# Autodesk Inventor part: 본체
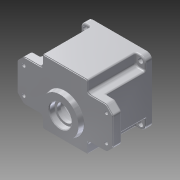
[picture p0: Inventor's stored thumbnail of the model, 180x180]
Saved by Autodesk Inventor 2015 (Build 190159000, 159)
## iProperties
Created: 2016-02
Part Number: 본체
Material: Aluminum 6061
Document SubType Name: Modeling
Designer: Administrator
Density: 2.7 g/cm^3
Appearance: Aluminum - Flat
Mass: 874.182 g
Surface Area: 763.255 cm^2
Volume: 323.771 cm^3
Author: Administrator
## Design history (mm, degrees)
sketch "Sketch1"
  geometry: L1 (-70, 30)-(-70, -30); L2 (70, -30)-(70, 30); L3 (33, 47)-(-33, 47); L4 (-33, -47)-(33, -47); L5 (70, 30)-(33, 30); L6 (-33, 30)-(-70, 30); L7 (33, -47)-(33, -30); L8 (33, 30)-(33, 47); L9 (-70, -30)-(-33, -30); L10 (33, -30)-(70, -30); L11 (-33, 47)-(-33, 30); L12 (-33, -30)-(-33, -47); 1 further point
  constraints: 24 end point, 10 parallel, 4 perpendicular, 3 collinear, 3 horizontal
  dimensions: "d0" = 140 distance between parallel lines of L1 L2; "d1" = 70 distance from line of point (0, 0) L2; "d2" = 94 distance between parallel lines of L4 L3; "d3" = 47 distance from line of L3 point (0, 0); "d4" = 66 distance between parallel lines of L11 L8; "d5" = 66 distance between parallel lines of L12 L7; "d6" = 33 distance from line of point (0, 0) L7; "d7" = 60 distance of L2.start L2.end; "d8" = 30 distance from line of point (0, 0) L5
extrude "Extrusion1" new body sketch "Sketch1" distance "d9" = 13; taper "d10" = 0 deg
sketch "Sketch2"
  geometry: L1 (-70, 30)-(-70, -30) reference; L2 (-70, -30)-(-33, -30) reference; L3 (-33, -30)-(-33, -47) reference; L4 (-33, -47)-(33, -47) reference; L5 (33, -47)-(33, -30) reference; L6 (33, -30)-(70, -30) reference; L7 (70, -30)-(70, 30) reference; L8 (70, 30)-(33, 30) reference; L9 (33, 30)-(33, 47) reference; L10 (33, 47)-(-33, 47) reference; L11 (-33, 47)-(-33, 30) reference; L12 (-33, 30)-(-70, 30) reference; L13 (47, 47)-(-47, 47); L14 (-47, 47)-(-47, -47); L15 (-47, -47)-(47, -47); L16 (47, -47)-(47, 47); L17 (47, 47)-(-47, -47); L18 (-47, 47)-(47, -47); 1 further point
  constraints: 12 end point, 2 midpoint, 2 parallel, 1 horizontal, 1 perpendicular
  dimensions: "d11" = 94 distance of L15.end L14.end; "d12" = 94 distance of L14.end L13.end
extrude "Extrusion2" join sketch "Sketch2" distance "d13" = 67; taper "d14" = 0 deg
sketch "Sketch4"
  geometry: L1 (-70, 30)-(-70, -30) reference; L2 (-70, -30)-(-33, -30) reference; L3 (-33, -30)-(-33, -47) reference; L4 (-33, -47)-(33, -47) reference; L5 (33, -47)-(33, -30) reference; L6 (33, -30)-(70, -30) reference; L7 (70, -30)-(70, 30) reference; L8 (70, 30)-(33, 30) reference; L9 (33, 30)-(33, 47) reference; L10 (33, 47)-(-33, 47) reference; L11 (-33, 47)-(-33, 30) reference; L12 (-33, 30)-(-70, 30) reference; L13 (-33, 30)-(-33, 47) reference; L14 (-47, 47)-(-33, 47) reference; L15 (-47, 30)-(-47, 47) reference; L16 (-47, 30)-(-33, 30) reference; L17 (33, 47)-(33, 30) reference; L18 (33, 30)-(47, 30) reference; L19 (47, 47)-(47, 30) reference; L20 (33, 47)-(47, 47) reference; L21 (47, -30)-(33, -30) reference; L22 (33, -30)-(33, -47) reference; L23 (47, -47)-(33, -47) reference; L24 (47, -30)-(47, -47) reference; L25 (-33, -30)-(-47, -30) reference; L26 (-47, -47)-(-47, -30) reference; L27 (-33, -47)-(-47, -47) reference; L28 (-33, -47)-(-33, -30) reference; 1 further point
extrude "Extrusion4" cut sketch "Sketch4" distance "d17" = 57; taper "d18" = 0 deg
sketch "Sketch5"
  geometry: L1 (-33, 47)-(-33, 30) reference; L2 (-47, 47)-(-33, 47) reference; L3 (-47, 30)-(-47, 47) reference; L4 (-33, 30)-(-47, 30) reference; L5 (33, 30)-(33, 47) reference; L6 (47, 30)-(33, 30) reference; L7 (47, 47)-(47, 30) reference; L8 (33, 47)-(47, 47) reference; L9 (33, -30)-(47, -30) reference; L10 (33, -47)-(33, -30) reference; L11 (47, -47)-(33, -47) reference; L12 (47, -30)-(47, -47) reference; L13 (-47, -30)-(-33, -30) reference; L14 (-47, -47)-(-47, -30) reference; L15 (-33, -47)-(-47, -47) reference; L16 (-33, -30)-(-33, -47) reference; L17 (-40, -40)-(40, -40); L18 (40, -40)-(40, 40); L19 (40, 40)-(-40, 40); L20 (-40, 40)-(-40, -40); L21 (-40, -40)-(40, 40); L22 (40, -40)-(-40, 40); 5 further points
  constraints: 12 end point, 4 coincident, 2 midpoint, 2 parallel, 1 horizontal, 1 perpendicular
  dimensions: "d20" = 80 distance of L19.end L18.end; "d21" = 80 distance of L18.end L17.end
hole "Hole1" sketch "Sketch5" at (-40, 40), (40, 40), (-40, -40), (40, -40) diameter "d22" = 7; stored, may be unused: countersink angle "d26" = 90 deg, drill point angle "d28" = 118 deg; dims "d23" = 6, "d24" = 4, "d25" = 2, "d27" = 8
fillet "Fillet1" dims "d29" = 8
sketch "Sketch6"
  geometry: C1 r 43 at (0, 0); 1 further point
  constraints: 1 centre point, 1 coincident
  dimensions: "d30" = 86 diameter of C1
extrude "Extrusion5" cut sketch "Sketch6" distance "d31" = 9; taper "d32" = 0 deg
sketch "Sketch7"
  geometry: C1 r 40 at (0, 0); 1 further point
  constraints: 1 centre point, 1 coincident
  dimensions: "d33" = 80 diameter of C1
extrude "Extrusion6" cut sketch "Sketch7" distance "d34" = 62; taper "d35" = 0 deg
sketch "Sketch8"
  geometry: A1 r 40 centre (0, 0) between (39.148, -8.214) and (39.148, 8.214) reference; A2 r 36 centre (0, 0) between (36, 0) and (35.778, -3.995); A3 r 4 centre (36, 0) between (35.852, 3.997) and (35.852, -3.997); A4 r 3.5 centre (35.722, 7.495) between (35.778, 3.995) and (39.148, 8.214); A5 r 3.5 centre (35.722, -7.495) between (39.148, -8.214) and (35.778, -3.995); A6 r 40 centre (0, 0) between (39.148, -8.214) and (39.148, 8.214); 1 further point
  constraints: 15 point on circle, 5 centre point, 5 tangent, 2 coincident, 1 horizontal alignment
  dimensions: "d36" = 72 diameter of A2; "d37" = 8 diameter of A3; "d38" = 7 diameter of A4; "d39" = 7 diameter of A5
extrude "Extrusion7" join sketch "Sketch8" distance "d40" = 62; taper "d41" = 0 deg
hole "Hole2" diameter "d44" = 3.242; stored, may be unused: countersink angle "d48" = 90 deg, drill point angle "d50" = 118 deg; dims "d42" = 10, "d43" = 10, "d45" = 7, "d46" = 4, "d47" = 2, "d49" = 9
mirror "Mirror1"
sketch "Sketch9"
  geometry: A1 r 3.5 centre (-35.722, -7.495) between (-35.852, -3.997) and (-39.148, -8.214) reference; A2 r 40 centre (0, 0) between (-39.148, -8.214) and (39.148, -8.214) reference; A3 r 3.5 centre (35.722, -7.495) between (39.148, -8.214) and (35.852, -3.997) reference; A4 r 4 centre (36, 0) between (35.852, 3.997) and (35.852, -3.997) reference; A5 r 3.5 centre (35.722, 7.495) between (35.852, 3.997) and (39.148, 8.214) reference; A6 r 40 centre (0, 0) between (39.148, 8.214) and (-39.148, 8.214) reference; A7 r 3.5 centre (-35.722, 7.495) between (-39.148, 8.214) and (-35.852, 3.997) reference; A8 r 4 centre (-36, 0) between (-35.852, -3.997) and (-35.852, 3.997) reference; A9 r 21 centre (0, 11) between (8.978, -7.984) and (-8.978, -7.984); A10 r 15 centre (0, -20) between (-8.978, -7.984) and (8.978, -7.984); 1 further point
  constraints: 4 point on circle, 2 centre point, 2 vertical alignment
  dimensions: "d51" = 42 diameter of A9; "d52" = 11 distance of point (0, 0) A9.centre; "d53" = 30 diameter of A10; "d54" = 20 distance of point (0, 0) A10.centre
extrude "Extrusion8" join sketch "Sketch9" distance "d55" = 7; taper "d56" = 0 deg
hole "Hole3" diameter "d59" = 19; stored, may be unused: countersink angle "d63" = 90 deg, drill point angle "d65" = 0 deg; dims "d57" = 10, "d58" = 10, "d60" = 7, "d61" = 22, "d62" = 7, "d64" = 8
sketch "Sketch10"
  geometry: C1 r 28 at (0, -11); A1 r 21 centre (0, -11) between (-8.978, 7.984) and (8.978, 7.984) reference; 1 further point
  constraints: 1 centre point, 1 coincident
  dimensions: "d66" = 56 diameter of C1
extrude "Extrusion9" join sketch "Sketch10" distance "d67" = 7; taper "d68" = -10 deg
hole "Hole4" diameter "d71" = 25; stored, may be unused: countersink angle "d75" = 90 deg, drill point angle "d77" = 0 deg; dims "d69" = 10, "d70" = 10, "d72" = 7, "d73" = 32, "d74" = 8, "d76" = 13
sketch "Sketch11"
  geometry: C1 r 11 at (0, -20) reference; C2 r 17.5 at (0, 11); A1 r 15 centre (0, -20) between (-8.978, -7.984) and (8.978, -7.984) reference; A2 r 21 centre (0, 11) between (8.978, -7.984) and (-8.978, -7.984) reference; 1 further point
  constraints: 1 centre point, 1 coincident
  dimensions: "d78" = 35 diameter of C2
extrude "Extrusion10" cut sketch "Sketch11" distance "d79" = 10; taper "d80" = 0 deg
fillet "Fillet2" dims "d81" = 0.3
fillet "Fillet3" dims "d82" = 2
chamfer "Chamfer1" distance "d83" = 10; stored, may be unused: second distance "d84" = 2, angle "d85" = 45 deg
chamfer "Chamfer2" distance "d86" = 10; stored, may be unused: second distance "d87" = 2, angle "d88" = 45 deg
sketch "Sketch13"
  geometry: L1 (70, -20)-(60, -30) reference; L2 (70, -20)-(70, 20) reference; L3 (60, 30)-(70, 20) reference; L4 (60, 30)-(33, 30) reference; L5 (33, 30)-(33, 47) reference; L6 (33, 47)-(-33, 47) reference; L7 (-33, 47)-(-33, 30) reference; L8 (-33, 30)-(-60, 30) reference; L9 (-70, 20)-(-60, 30) reference; L10 (-70, 20)-(-70, -20) reference; L11 (-60, -30)-(-70, -20) reference; L12 (-60, -30)-(-33, -30) reference; L13 (-33, -30)-(-33, -47) reference; L14 (-33, -47)-(33, -47) reference; L15 (33, -47)-(33, -30) reference; L16 (33, -30)-(60, -30) reference; L17 (32, -46)-(-32, -46); L18 (-32, -46)-(-32, -29); L19 (-32, -29)-(-59.586, -29); L20 (-59.586, -29)-(-69, -19.586); L21 (-69, -19.586)-(-69, 19.586); L22 (-69, 19.586)-(-59.586, 29); L23 (-59.586, 29)-(-32, 29); L24 (-32, 29)-(-32, 46); L25 (-32, 46)-(32, 46); L26 (32, 46)-(32, 29); L27 (32, 29)-(59.586, 29); L28 (59.586, 29)-(69, 19.586); L29 (69, 19.586)-(69, -19.586); L30 (69, -19.586)-(59.586, -29); L31 (59.586, -29)-(32, -29); L32 (32, -29)-(32, -46); C1 r 28 at (0, -11) reference; A1 r 4 centre (36, 0) between (35.852, 3.997) and (35.852, -3.997) reference; 1 further point
  constraints: 32 end point, 15 other
  dimensions: "d89" = 1 distance between parallel lines of L14 L17
extrude "Extrusion11" cut sketch "Sketch13" distance "d90" = 1; taper "d91" = 0 deg
sketch "Sketch14"
  geometry: L1 (-60, 19)-(60, 19); L2 (60, 19)-(60, -19); L3 (60, -19)-(-60, -19); L4 (-60, -19)-(-60, 19); L5 (-60, 19)-(60, -19); L6 (60, 19)-(-60, -19); 5 further points
  constraints: 12 end point, 4 coincident, 2 midpoint, 2 parallel, 1 horizontal, 1 perpendicular
  dimensions: "d92" = 120 distance of L2.end L3.end; "d93" = 38 distance of L1.end L2.end
hole "Hole5" sketch "Sketch14" at (-60, 19), (60, 19), (60, -19), (-60, -19) diameter "d94" = 5; stored, may be unused: countersink angle "d98" = 90 deg, drill point angle "d100" = 0 deg; dims "d95" = 7, "d96" = 9, "d97" = 4, "d99" = 13
sketch "Sketch15"
  geometry: L1 (0, 0)-(78, 0) reference; 2 further points
  constraints: 1 vertical alignment, 1 other
  dimensions: "d101" = 40 distance from line of point (39, -40) L1
emboss "Emboss1" sketch "Sketch15" dims "d102" = 0.5, "d103" = 0
fillet "Fillet4" dims "d104" = 2
fillet "Fillet5" dims "d105" = 2
fillet "Fillet6" dims "d106" = 2
fillet "Fillet7" dims "d107" = 3
fillet "Fillet8" dims "d108" = 2
chamfer "Chamfer3" distance "d109" = 1; stored, may be unused: second distance "d110" = 2, angle "d111" = 45 deg
fillet "Fillet9" dims "d112" = 5
fillet "Fillet10" dims "d113" = 4
fillet "Fillet11" dims "d114" = 5
fillet "Fillet12" dims "d115" = 4
fillet "Fillet13" dims "d116" = 0.3
fillet "Fillet14" dims "d117" = 0.3
body "Solid1"
node "Projected Loop1"
node "Projected Loop6"
node "Projected Loop7"
node "Projected Loop8"
node "Projected Loop9"
node "Projected Loop10"
node "Projected Loop11"
node "Projected Loop12"
node "Projected Loop13"
node "Projected Loop14"
node "Projected Loop15"
node "Projected Loop16"
node "Projected Loop17"
node "Projected Loop18"
